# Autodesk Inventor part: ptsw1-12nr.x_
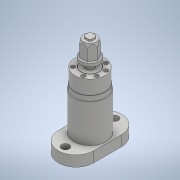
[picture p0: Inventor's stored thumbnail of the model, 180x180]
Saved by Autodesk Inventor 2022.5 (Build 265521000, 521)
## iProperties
Part Number: ptsw1-12nr.x_
Material: 一般
Document SubType Name: Modeling
Designer: ImaoCorp
Density: 1 g/cm^3
Appearance: 既定
Sending System: SOLIDWORKS 2017-2017317
MC: AMD64
MC_MODEL: Intel64 Family 6 Model 60 Stepping 3, GenuineIntel
OS: Windows_NT
FRU: Parasolid Version 29.0, build 201,  4-17-2017
FORMAT: text
GUISE: transmit
KEY: ptsw1-12nr
FILE: ptsw1-12nr.x_t
DATE: Wed Sep 04 15:22:24 2019
Author: ImaoCorp
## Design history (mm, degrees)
feature "Base1"
node "ソリッド1"
